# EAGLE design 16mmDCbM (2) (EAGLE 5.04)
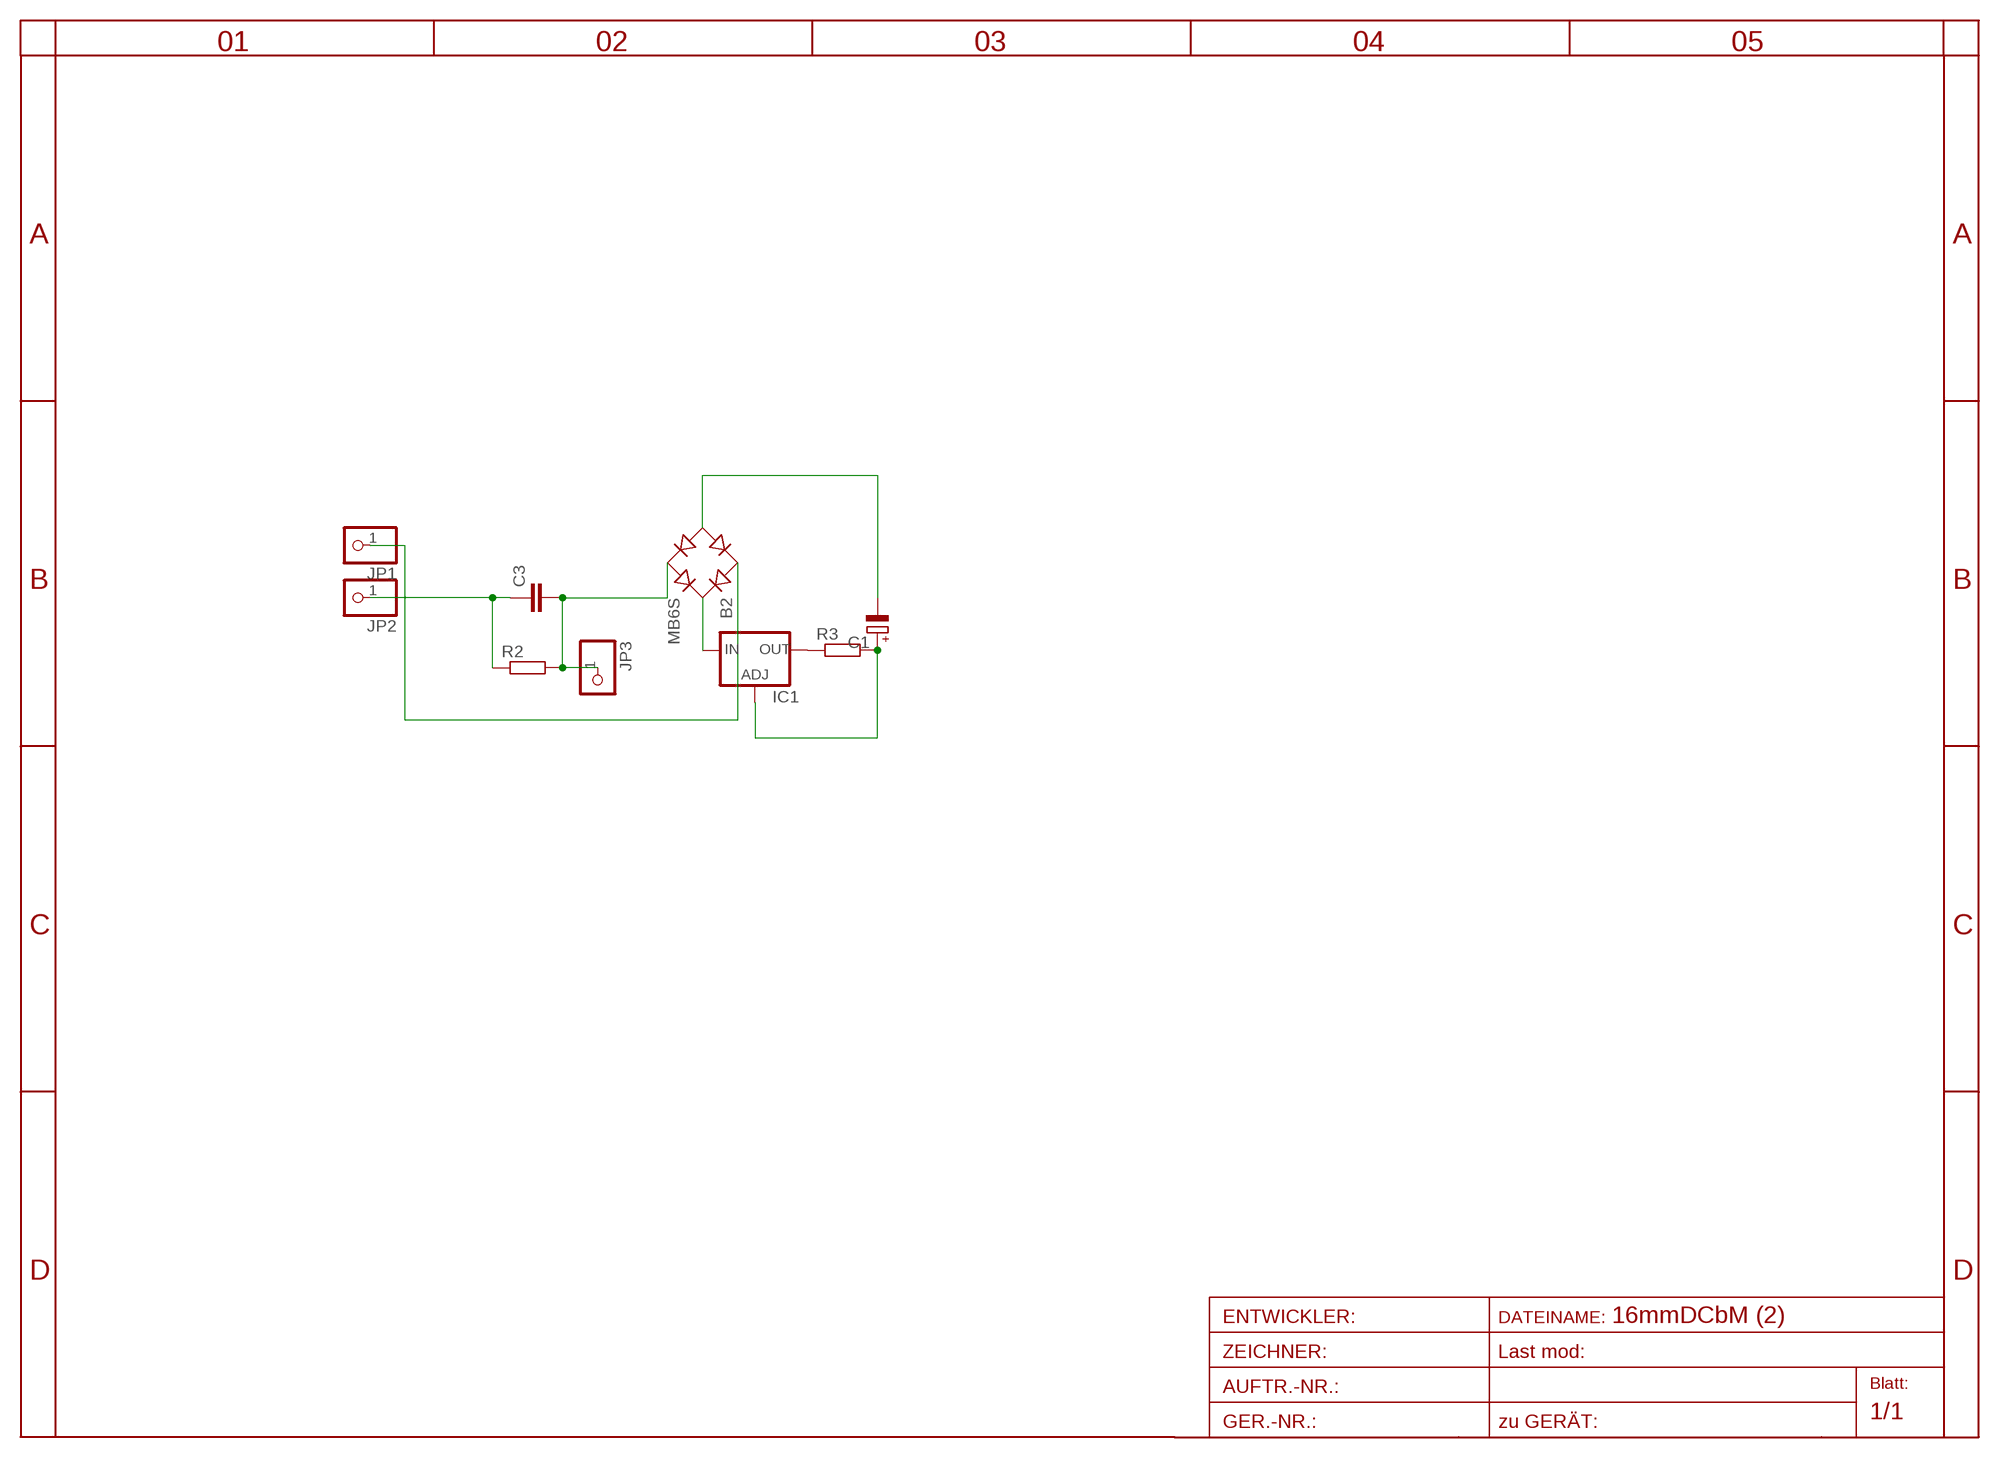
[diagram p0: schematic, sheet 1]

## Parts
B2  MB6S  [SOIC-4]
C1  CPOL-EUE5-8.5  [E5-8,5]
C3  C-EU102-064X133  [C102-064X133]
IC1  LM317LZ  [317L]
JP1  PINHD-1X1  [1X01]
JP2  PINHD-1X1  [1X01]
JP3  PINHD-1X1  [1X01]
R2  R-EU_R1206  [R1206]
R3  R-EU_0204/2V  [0204V]

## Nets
AC: B2.~1(AC1) JP1.1
AC+: C3.1 JP2.1 R2.1
N$1: B2.~2(AC2) C3.2 JP3.1 R2.2
N$2: B2.+ IC1.3(IN)
N$5: IC1.2(OUT) R3.1
N$9: B2.- C1.-
PLUS: C1.+ IC1.1(ADJ) R3.2

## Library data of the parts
B2 = rectifier:MB*S: Bridge Rectifier Source: http://www.fairchildsemi.com/ds/MB/MB6S.pdf
C1 = rcl-2:CPOL-EU: POLARIZED CAPACITOR, European symbol
C3 = rcl:C-EU: CAPACITOR, European symbol
IC1 = v-reg-3:LM317L: Adjustable Voltage Regulator, 1.2V to 37V, 100mA
JP1-JP3 = pinhead:PINHD-1X1: PIN HEADER
R2 R3 = rcl:R-EU_: RESISTOR, European symbol

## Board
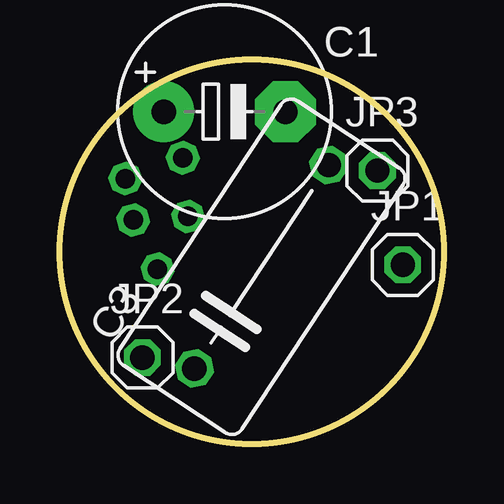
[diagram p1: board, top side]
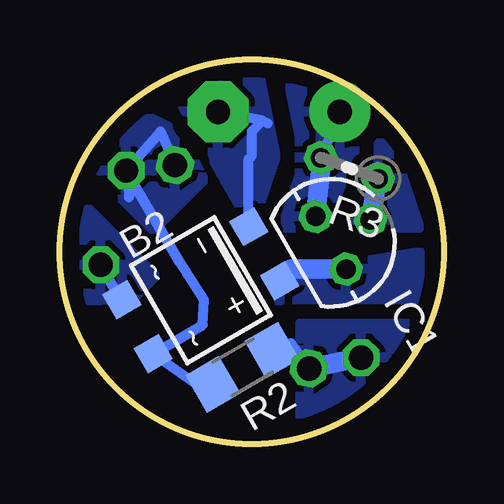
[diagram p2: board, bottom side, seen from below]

Size 16 x 16 mm. Coordinates in mm from the lower left corner, seen from the top.
Outline: circle at 8,8 radius 8
Copper layers (1*16): Top 0.035mm / dielectric 1.5mm / Bottom 0.035mm
Design rules "default *": minimum track width 10mil, minimum drill 24mil, track to track 8mil, track to pad 8mil, pad to pad 8mil, via to via 8mil, smd to smd 8mil, copper to edge 4mil, drill to drill 8mil, minimum pad ring 10mil, minimum via ring 8mil, stop-mask expansion 4mil, vias tented up to drill 0mil, thermal gap 10mil

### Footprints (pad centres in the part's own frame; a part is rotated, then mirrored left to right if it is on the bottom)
SOIC-4 = smd 1.2 x 1.2: + 1.3,3.05; - -1.3,3.05; ~1 -1.3,-3.05; ~2 1.3,-3.05
E5-8,5 = drill 1.016 pad 2.54 round: + -2.54,0 | drill 1.016 pad 2.54 octagon: - 2.54,0
C102-064X133 = drill 1.016 octagon: 1 -5.08,0; 2 5.08,0
317L = drill 0.813 octagon: 1 -1.27,0; 2 0,1.905; 3 1.27,0
1X01 = drill 1.016 octagon: 1 0,0
R1206 = smd 1.6 x 1.803: 1 -1.422,0; 2 1.422,0
0204V = drill 0.813 octagon: 1 -1.27,0; 2 1.27,0

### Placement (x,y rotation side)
B2  10.12,6.4 300 bottom
C1  6.87,13.84 0 top
C3  8.41,7.37 56.6 top
IC1  4.71,8.37 300 bottom
JP1  14.3,7.46 0 top
JP2  3.44,3.59 0 top
JP3  13.24,11.38 0 top
R2  8.39,3.18 210 bottom
R3  3.93,11.49 160 bottom

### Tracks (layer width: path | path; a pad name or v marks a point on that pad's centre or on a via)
AC
  Bottom 0.406: B2.~1 13.44,6 JP1.1
  pour Bottom (isolate 0.61): 13,8 15,10 15,6 13,6 12,7
AC+
  Bottom 0.406: R2.1 6.35,4.19 C3.1
  Bottom 0.813: JP2.1 C3.1
  pour Bottom (isolate 0.61): 1,5 6,5 6,0 3,2
N$1
  Bottom 0.406: C3.2 11.81,13.01 JP3.1 | JP3.1 13.12,10.27 | R2.2 10.02,2.25 B2.~2 10.05,4.95 10,6 11,7.54 JP3.1
  pour Bottom (isolate 0.61, rank 2): 11,13 10,11 13,8 16,8 16,11 13,14
N$2
  Bottom 0.406: IC1.3 4.36,7.38 | 6.36,7.27 B2.+
  Bottom 0.813: IC1.3 6.36,7.27
  pour Bottom (isolate 0.61, rank 3): 1,8 7,7 7,6 1,6
N$5
  Bottom 0.406: 2.85,10.39 R3.1
  Bottom 0.813: IC1.2 2.85,10.39
  pour Bottom (isolate 0.61, rank 4): 2,12 1,9 4,9 3,13
N$9
  Bottom 0.406: 7.55,13.48 7.33,13.36 | 7.55,13.48 C1.- | B2.- 8.13,11.87 8,12 8,13.03 7.55,13.48
  pour Bottom (isolate 0.61, rank 2): 7,12 8,17 12,16 8,9
PLUS
  Bottom 0.406: 5.14,11.32 R3.2 4.42,13.53 C1.+
  Bottom 0.813: IC1.1 5.14,11.32
  pour Bottom (isolate 0.61, rank 3): 3,14 5,9 7,9 7,15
